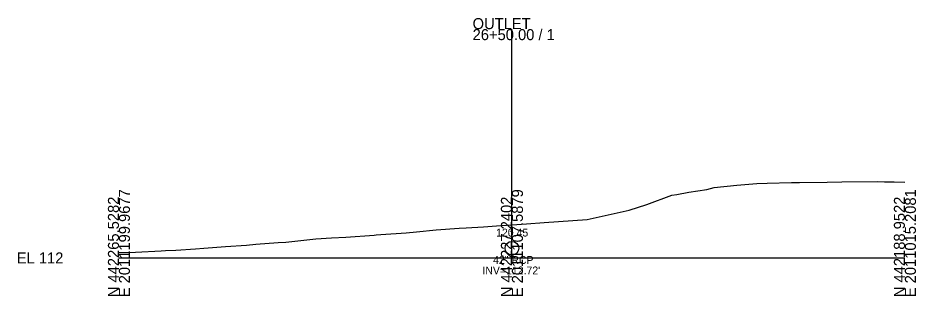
# Model space of a CAD drawing. Extents: x -26 to 1203, y -15 to 9526.
# Drawn here: x 974.3 to 1202.8, y 6490.3 to 6561.1 of the extents above; entities that cross this region are included whole.
import ezdxf

# ---------------------------------------------------------------- set-up
doc = ezdxf.new("R2010")
doc.units = 0
for name, color, linetype in [('Exist Cross Section Cell', 7, 'Continuous'), ('Exist XS Center Line Elevation Label', 7, 'Continuous'), ('Exist XS Ground Line', 7, 'Continuous'), ('Prop XSC Text', 7, 'Continuous')]:
    doc.layers.add(name, color=color, linetype=linetype)

msp = doc.modelspace()

# ---------------------------------------------------------------- linework, layer by layer
at = {"layer": 'Exist Cross Section Cell'}
for p, q in [((1100, 6500), (1100, 6558.22)), ((1000, 6500), (1100, 6500)), ((1100, 6500), (1200, 6500))]:
    msp.add_line(p, q, dxfattribs=at)
at = {"layer": 'Exist XS Ground Line'}
msp.add_lwpolyline([(1000, 6501.39), (1004.21, 6501.46), (1010.79, 6501.79), (1011.86, 6501.86), (1014.44, 6502.02), (1019.51, 6502.36), (1021.61, 6502.51), (1027.16, 6502.93), (1032.44, 6503.26), (1034.82, 6503.48), (1040.56, 6503.89), (1042.47, 6504.04), (1043.26, 6504.09), (1050.12, 6504.84), (1054.09, 6505.11), (1057.78, 6505.29), (1064.91, 6505.81), (1065.43, 6505.86), (1066.67, 6505.94), (1073.08, 6506.42), (1075.74, 6506.65), (1080.74, 6507.17), (1086.56, 6507.58), (1088.39, 6507.65), (1092.79, 6507.93), (1096.04, 6508.14), (1097.39, 6508.26), (1100, 6508.45), (1103.69, 6508.71), (1108.21, 6509.01), (1119.13, 6509.79), (1129.86, 6512.16), (1134.31, 6513.57), (1140.69, 6515.95), (1141.96, 6516.14), (1145.03, 6516.73), (1149.61, 6517.38), (1151.51, 6517.9), (1157.27, 6518.48), (1162.34, 6518.92), (1164.92, 6519.02), (1171.15, 6519.19), (1173.16, 6519.23), (1180.22, 6519.29), (1183.99, 6519.39), (1193.08, 6519.41), (1194.81, 6519.4), (1197.26, 6519.36), (1200, 6519.26)], dxfattribs=at)
at = {"layer": 'Prop XSC Text'}
msp.add_circle((1100, 6502.47), 1.75, dxfattribs=at)

# ---------------------------------------------------------------- texts
at = {"layer": 'Exist Cross Section Cell'}
for s, p in [('OUTLET', (1090, 6558.22)), ('26+50.00 / 1', (1090, 6555.42)), ('EL 112', (974, 6498.6))]:
    msp.add_text(s, height=2.8, dxfattribs=at).set_placement(p)
for s, p in [('E 2011199.9677', (1002.8, 6490)), ('E 2011107.5879', (1102.8, 6490)), ('E 2011015.2081', (1202.8, 6490)), ('N 442265.5282', (1000, 6490)), ('N 442227.2402', (1100, 6490)), ('N 442188.9522', (1200, 6490))]:
    msp.add_text(s, height=2.8, rotation=90, dxfattribs=at).set_placement(p)
at = {"layer": 'Exist XS Center Line Elevation Label'}
msp.add_text('120.45', height=2, dxfattribs=at).set_placement((1095.98, 6505.45))
at = {"layer": 'Prop XSC Text'}
for s, p in [('42" RCP', (1095.2, 6498.48)), ("INV=112.72'", (1092.49, 6495.82))]:
    msp.add_text(s, height=2, dxfattribs=at).set_placement(p)

doc.saveas('drawing.dxf')
